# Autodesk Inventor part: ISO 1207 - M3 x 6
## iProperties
Created: 2004-01
Part Number: ISO 1207 - M3 x 6
Material: Standard
Catalog Web Link: file:///C:/Programme/Autodesk/Inventor 5.3/Content/Din/index.htm?doNavigateId=7A3AD6BF-C431-11D4-A9F1-0080AD303E0A|311999C6B16811D4BA6900C04F798F98|true
Description: Zylinderschraube mit Schlitz
Document SubType Name: Standard Catalog Part
Standard: ISO 1207 - M3 x 6
Designer: Ulrich
Control State: 0
Master: False
Checked Out: False
Shininess: 20.0
Angle Display Precision: 2
Document Length Units: 11269
Document Angle Units: 11279
Document Time Units: 11290
Document Mass Units: 11283
Document Length Units Precision: 3
Document Angle Units Precision: 2
Compacted: True
KLASSIFIKATION: 31161501 un/spsc
HERSTELLER: DIN Normsystem
Density: 0.0
Volumn: 0.0
Area: 0.0
PropertySet Name: Model Information
Author: Ulrich
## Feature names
1. Basis1
